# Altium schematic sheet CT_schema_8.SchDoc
size 287 x 160 mm
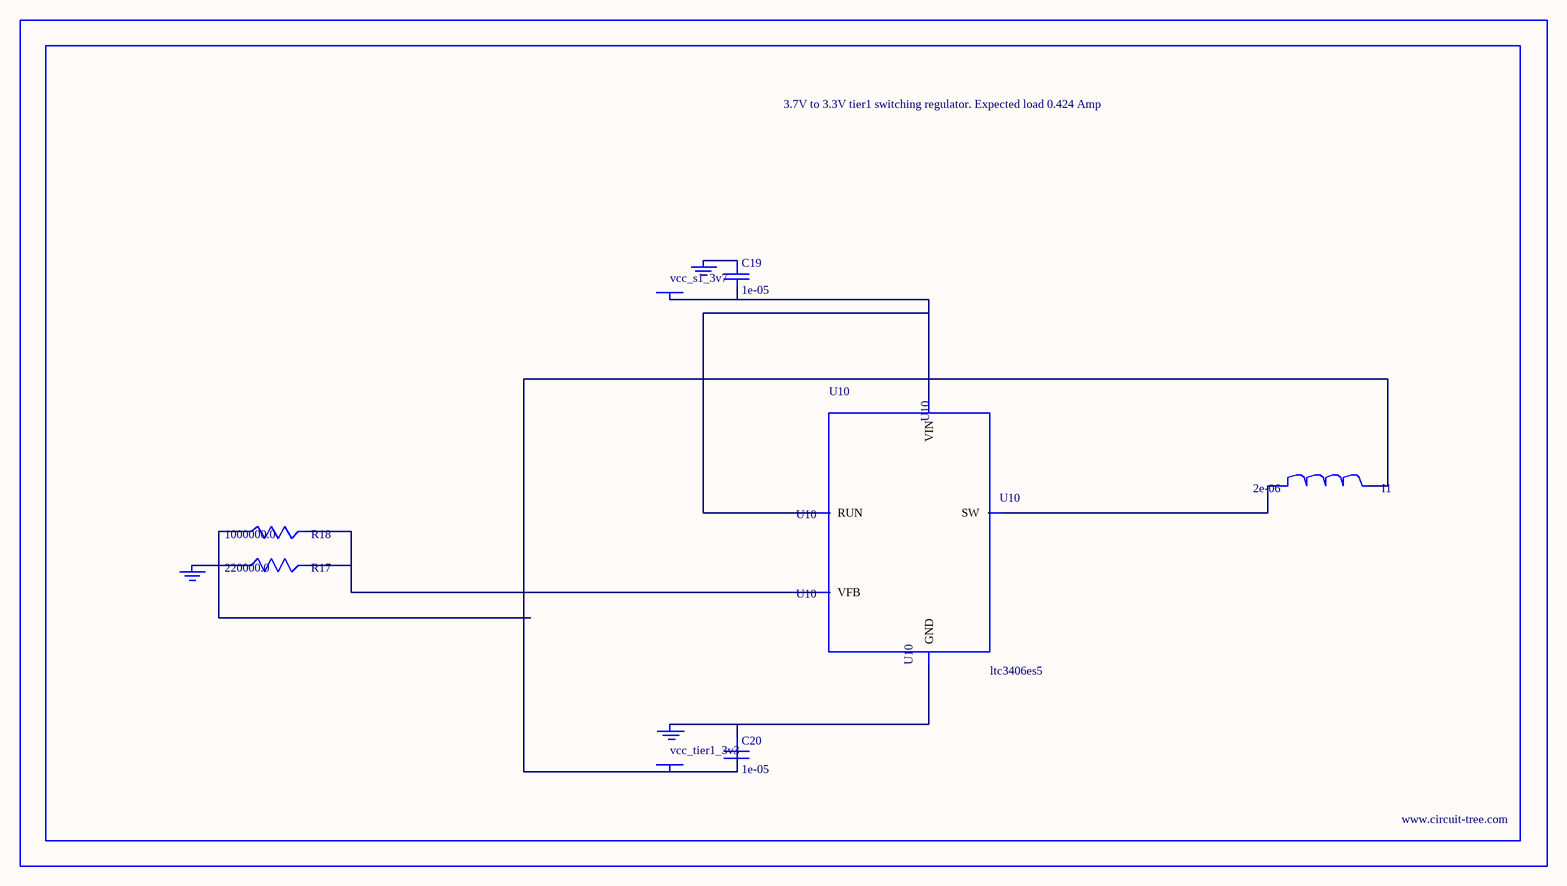
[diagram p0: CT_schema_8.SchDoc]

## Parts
BORDER7  (no value)
C19  1e-05  [C0805]
C20  1e-05  [C0805]
GND_INSTANCE_7_0  (no value)
GND_INSTANCE_7_1  (no value)
GND_INSTANCE_7_2  (no value)
I1  2e-06  [WE-HCI_7030/7040/7050]
POWER_INSTANCE_7_0  vcc_tier1_3v3
POWER_INSTANCE_7_1  vcc_s1_3v7
R17  220000.0  [R0603]
R18  1000000.0  [R0603]
U10  ltc3406es5  [TSOT-23-5]

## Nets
NetC19_1: C19.1 GND_INSTANCE_7_1.0(GND)
NetC19_2: C19.2 POWER_INSTANCE_7_1.0(PWR) U10.1(RUN) U10.4(VIN)
NetC20_1: C20.1 GND_INSTANCE_7_0.0(GND) U10.2(GND)
NetC20_2: C20.2 I1.2 POWER_INSTANCE_7_0.0(PWR) R18.1
NetGND_INSTANCE_7_2_0: GND_INSTANCE_7_2.0(GND) R17.1
NetI1_1: I1.1 U10.3(SW)
NetR17_2: R17.2 R18.2 U10.5(VFB)

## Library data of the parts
BORDER7 = BORDER_PAGE7
C19 C20 = C0805C106K8RACTU
GND_INSTANCE_7_0-GND_INSTANCE_7_2 = GND
I1 = 744314200
POWER_INSTANCE_7_0 POWER_INSTANCE_7_1 = PWR
R17 = RC0603JR-07220KL
R18 = RC0603JR-071ML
